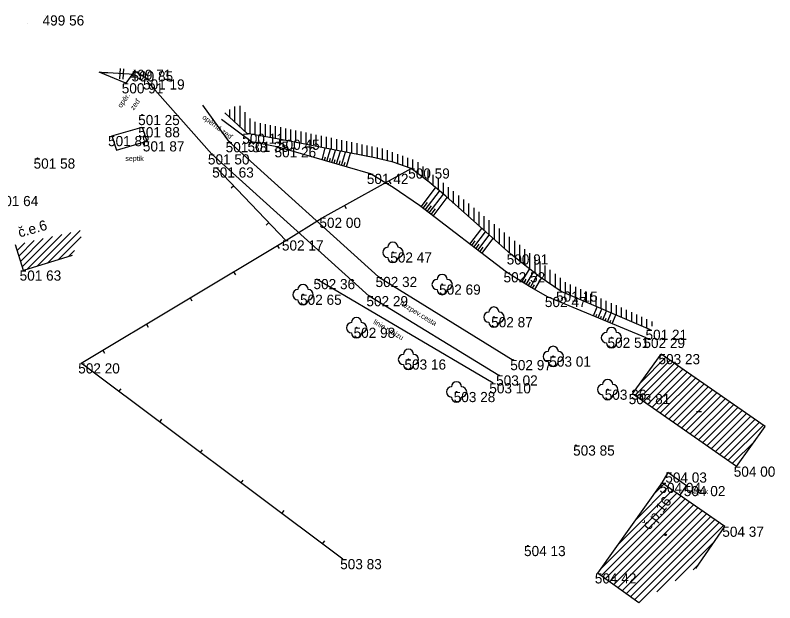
# Model space of a CAD drawing. Extents: x -554123 to -553118, y -1076825 to -1073672.
# Drawn here: x -553192.3 to -553117.7, y -1076813.9 to -1076756.1 of the extents above; entities that cross this region are included whole.
import ezdxf

# ---------------------------------------------------------------- set-up
doc = ezdxf.new("R2010")
doc.units = 0
for name, color, linetype in [('1', 7, 'Continuous'), ('12', 7, 'Continuous'), ('14', 7, 'Continuous'), ('17', 7, 'Continuous'), ('18', 7, 'Continuous'), ('26', 7, 'Continuous'), ('27', 7, 'Continuous'), ('28', 7, 'Continuous'), ('32', 7, 'Continuous'), ('34', 7, 'Continuous'), ('47', 7, 'Continuous'), ('52', 7, 'Continuous'), ('54', 7, 'Continuous'), ('6', 7, 'Continuous'), ('62', 7, 'Continuous')]:
    doc.layers.add(name, color=color, linetype=linetype)

# ---------------------------------------------------------------- blocks, each defined once
blk = doc.blocks.new('POINT_DISPLAY')
blk.add_line((0, 0), (0, 0))
blk = doc.blocks.new('T')
at = {"layer": '6'}
blk.add_circle((0, 0), 0.05, dxfattribs=at)
blk = doc.blocks.new('STL')
at = {"layer": '34'}
blk.add_circle((0, 0), 0.05, dxfattribs=at)
for centre, start, end in [((0, 0.5), 0, 180), ((-0.5, 0), 90, 270), ((0.5, 0), 270, 90), ((0, -0.5), 180, 0)]:
    blk.add_arc(centre, 0.5, start, end, dxfattribs=at)
blk = doc.blocks.new('BZ')
at = {"layer": '47'}
blk.add_circle((0, 0), 0.0875, dxfattribs=at)
blk = doc.blocks.new('BN')
at = {"layer": '47'}
blk.add_line((-0.25, 0), (0.25, 0), dxfattribs=at)
blk = doc.blocks.new('ROV')
at = {"layer": '62'}
for p, q in [((-0.348, -0.51), (-0.348, 0.51)), ((0, -0.51), (0, 0.51))]:
    blk.add_line(p, q, dxfattribs=at)

msp = doc.modelspace()

# ---------------------------------------------------------------- linework, layer by layer
at = {"layer": '12'}
for p, q in [((-553172.57, -1076771.05), (-553165.73, -1076778.23)), ((-553162.15, -1076776), (-553153.41, -1076771.15)), ((-553170.846, -1076772.86), (-553171.099, -1076773.102)), ((-553155.592, -1076772.361), (-553155.422, -1076772.667)), ((-553159.964, -1076774.787), (-553159.794, -1076775.093)), ((-553165.73, -1076778.23), (-553162.15, -1076776)), ((-553167.397, -1076776.48), (-553167.65, -1076776.722)), ((-553185.86, -1076790.32), (-553165.73, -1076778.23)), ((-553166.571, -1076778.735), (-553166.391, -1076779.035)), ((-553170.858, -1076781.31), (-553170.678, -1076781.61)), ((-553175.144, -1076783.884), (-553174.964, -1076784.184)), ((-553179.43, -1076786.458), (-553179.25, -1076786.759)), ((-553183.717, -1076789.033), (-553183.537, -1076789.333)), ((-553160.11, -1076809.58), (-553185.86, -1076790.32)), ((-553182.132, -1076793.109), (-553181.922, -1076792.828)), ((-553178.128, -1076796.104), (-553177.918, -1076795.823)), ((-553174.124, -1076799.098), (-553173.914, -1076798.818)), ((-553170.12, -1076802.093), (-553169.91, -1076801.813)), ((-553166.116, -1076805.088), (-553165.906, -1076804.808)), ((-553162.112, -1076808.083), (-553161.902, -1076807.802))]:
    msp.add_line(p, q, dxfattribs=at)
at = {"layer": '14'}
for p, q in [((-553191.5, -1076781.19), (-553192.288, -1076778.654)), ((-553186.725, -1076779.706), (-553191.5, -1076781.19)), ((-553131.64, -1076793.34), (-553128.82, -1076789.41)), ((-553118.61, -1076796.55), (-553128.82, -1076789.41)), ((-553121.43, -1076800.48), (-553131.64, -1076793.34)), ((-553121.43, -1076800.48), (-553118.61, -1076796.55)), ((-553128.75, -1076802.08), (-553135.1, -1076810.98)), ((-553122.56, -1076806.39), (-553128.75, -1076802.08)), ((-553125.417, -1076810.493), (-553122.56, -1076806.39)), ((-553131.03, -1076813.884), (-553135.1, -1076810.98))]:
    msp.add_line(p, q, dxfattribs=at)
at = {"layer": '17'}
for p, q in [((-553173, -1076769.76), (-553179.37, -1076762.58)), ((-553171.26, -1076768.56), (-553173.9, -1076764.93)), ((-553171.26, -1076768.56), (-553156.63, -1076781.82)), ((-553157.52, -1076783.71), (-553173, -1076769.76)), ((-553156.63, -1076781.82), (-553143.38, -1076790)), ((-553144.78, -1076791.51), (-553157.52, -1076783.71))]:
    msp.add_line(p, q, dxfattribs=at)
at = {"layer": '18'}
for p, q in [((-553180.62, -1076761.59), (-553181.46, -1076762.77)), ((-553179.26, -1076762.39), (-553180.62, -1076761.59)), ((-553169.11, -1076768.52), (-553172.04, -1076766.33)), ((-553182.82, -1076767.96), (-553179.85, -1076767.09)), ((-553179.85, -1076767.09), (-553179.4, -1076768.48)), ((-553182.82, -1076767.96), (-553182.37, -1076769.35)), ((-553182.37, -1076769.35), (-553179.4, -1076768.48)), ((-553169.307, -1076768.784), (-553169.11, -1076768.52)), ((-553128.16, -1076801.06), (-553128.75, -1076802.08)), ((-553126.34, -1076802.39), (-553128.16, -1076801.06)), ((-553126.982, -1076803.311), (-553126.34, -1076802.39))]:
    msp.add_line(p, q, dxfattribs=at)
at = {"layer": '26'}
for p, q in [((-553162.172, -1076770.296), (-553161.845, -1076769.165)), ((-553161.692, -1076770.435), (-553161.352, -1076769.26)), ((-553161.211, -1076770.574), (-553160.858, -1076769.355)), ((-553161.932, -1076770.365), (-553161.832, -1076770.02)), ((-553160.731, -1076770.713), (-553160.365, -1076769.45)), ((-553160.251, -1076770.852), (-553159.873, -1076769.545)), ((-553159.771, -1076770.991), (-553159.38, -1076769.64)), ((-553161.451, -1076770.504), (-553161.348, -1076770.145)), ((-553160.971, -1076770.643), (-553160.863, -1076770.271)), ((-553160.491, -1076770.782), (-553160.379, -1076770.397)), ((-553160.011, -1076770.921), (-553159.895, -1076770.523)), ((-553152.436, -1076774.918), (-553151, -1076773.048)), ((-553152.039, -1076775.223), (-553150.617, -1076773.373)), ((-553151.643, -1076775.527), (-553150.236, -1076773.696)), ((-553152.238, -1076775.07), (-553151.809, -1076774.512)), ((-553151.246, -1076775.832), (-553149.858, -1076774.025)), ((-553151.841, -1076775.375), (-553151.417, -1076774.823)), ((-553151.445, -1076775.679), (-553151.025, -1076775.133)), ((-553147.655, -1076778.591), (-553146.472, -1076777.051)), ((-553147.258, -1076778.895), (-553146.098, -1076777.385)), ((-553147.457, -1076778.743), (-553147.105, -1076778.286)), ((-553146.862, -1076779.2), (-553145.724, -1076777.719)), ((-553146.465, -1076779.505), (-553145.35, -1076778.054)), ((-553147.06, -1076779.048), (-553146.715, -1076778.599)), ((-553146.664, -1076779.352), (-553146.326, -1076778.912)), ((-553142.543, -1076782.295), (-553141.768, -1076781.047)), ((-553142.118, -1076782.559), (-553141.372, -1076781.357)), ((-553141.692, -1076782.82), (-553141.014, -1076781.637)), ((-553141.258, -1076783.069), (-553140.607, -1076781.933)), ((-553142.331, -1076782.427), (-553142.103, -1076782.06)), ((-553141.906, -1076782.691), (-553141.686, -1076782.337)), ((-553141.475, -1076782.944), (-553141.277, -1076782.598)), ((-553135.498, -1076785.658), (-553135.131, -1076784.774)), ((-553135.036, -1076785.85), (-553134.671, -1076784.971)), ((-553135.267, -1076785.754), (-553135.157, -1076785.49)), ((-553134.805, -1076785.946), (-553134.696, -1076785.683)), ((-553134.575, -1076786.042), (-553134.212, -1076785.167)), ((-553134.113, -1076786.233), (-553133.752, -1076785.364)), ((-553133.651, -1076786.425), (-553133.292, -1076785.56)), ((-553134.344, -1076786.138), (-553134.235, -1076785.876)), ((-553133.882, -1076786.329), (-553133.774, -1076786.069))]:
    msp.add_line(p, q, dxfattribs=at)
at = {"layer": '27'}
for p, q in [((-553181.46, -1076762.77), (-553184.07, -1076761.67)), ((-553166.44, -1076769.06), (-553169.11, -1076768.52)), ((-553157.39, -1076771.68), (-553166.44, -1076769.06)), ((-553130.29, -1076787.82), (-553140, -1076783.79))]:
    msp.add_line(p, q, dxfattribs=at)
for points in [[(-553144.05, -1076781.36), (-553152.579, -1076774.808), (-553155.161, -1076773.03), (-553157.39, -1076771.68)], [(-553140, -1076783.79), (-553141.772, -1076782.774), (-553144.05, -1076781.36)]]:
    msp.add_lwpolyline(points, dxfattribs=at)
at = {"layer": '28'}
for p, q in [((-553169.52, -1076767.73), (-553171.73, -1076765.67)), ((-553166.23, -1076768.32), (-553169.52, -1076767.73)), ((-553129.88, -1076787.02), (-553138.67, -1076783.26))]:
    msp.add_line(p, q, dxfattribs=at)
for points in [[(-553153.41, -1076771.15), (-553155.178, -1076770.537), (-553156.983, -1076770.102), (-553166.23, -1076768.32)], [(-553143.62, -1076779.6), (-553150.015, -1076773.884), (-553151.637, -1076772.507), (-553153.41, -1076771.15)], [(-553138.67, -1076783.26), (-553140.831, -1076781.78), (-553143.62, -1076779.6)]]:
    msp.add_lwpolyline(points, dxfattribs=at)
at = {"layer": '32'}
for p, q in [((-553171.23, -1076766.136), (-553171.23, -1076765.357)), ((-553170.73, -1076766.602), (-553170.73, -1076765.045)), ((-553170.23, -1076767.068), (-553170.23, -1076764.994)), ((-553169.73, -1076767.534), (-553169.73, -1076765.617)), ((-553169.23, -1076767.782), (-553169.23, -1076766.24)), ((-553168.73, -1076767.872), (-553168.73, -1076766.58)), ((-553168.23, -1076767.961), (-553168.23, -1076766.685)), ((-553167.73, -1076768.051), (-553167.73, -1076766.79)), ((-553167.23, -1076768.141), (-553167.23, -1076766.895)), ((-553166.73, -1076768.23), (-553166.73, -1076767)), ((-553166.23, -1076768.32), (-553166.23, -1076767.105)), ((-553165.73, -1076768.416), (-553165.73, -1076767.21)), ((-553165.23, -1076768.513), (-553165.23, -1076767.315)), ((-553164.73, -1076768.609), (-553164.73, -1076767.42)), ((-553164.23, -1076768.705), (-553164.23, -1076767.525)), ((-553163.73, -1076768.802), (-553163.73, -1076767.63)), ((-553163.23, -1076768.898), (-553163.23, -1076767.735)), ((-553162.73, -1076768.994), (-553162.73, -1076767.84)), ((-553162.23, -1076769.091), (-553162.23, -1076767.945)), ((-553161.73, -1076769.187), (-553161.73, -1076768.05)), ((-553161.23, -1076769.284), (-553161.23, -1076768.155)), ((-553160.73, -1076769.38), (-553160.73, -1076768.26)), ((-553160.23, -1076769.476), (-553160.23, -1076768.366)), ((-553159.73, -1076769.573), (-553159.73, -1076768.471)), ((-553159.23, -1076769.669), (-553159.23, -1076768.576)), ((-553158.73, -1076769.765), (-553158.73, -1076768.681)), ((-553158.23, -1076769.862), (-553158.23, -1076768.786)), ((-553157.73, -1076769.958), (-553157.73, -1076768.891)), ((-553157.23, -1076770.054), (-553157.23, -1076768.996)), ((-553156.73, -1076770.163), (-553156.73, -1076769.101)), ((-553156.23, -1076770.283), (-553156.23, -1076769.206)), ((-553155.73, -1076770.404), (-553155.73, -1076769.37)), ((-553155.23, -1076770.524), (-553155.23, -1076769.553)), ((-553154.73, -1076770.692), (-553154.73, -1076769.737)), ((-553154.23, -1076770.866), (-553154.23, -1076769.92)), ((-553153.73, -1076771.039), (-553153.73, -1076770.104)), ((-553153.23, -1076771.288), (-553153.23, -1076770.287)), ((-553152.73, -1076771.67), (-553152.73, -1076770.549)), ((-553152.23, -1076772.053), (-553152.23, -1076770.955)), ((-553151.73, -1076772.436), (-553151.73, -1076771.362)), ((-553151.23, -1076772.853), (-553151.23, -1076771.768)), ((-553150.73, -1076773.277), (-553150.73, -1076772.175)), ((-553150.23, -1076773.701), (-553150.23, -1076772.581)), ((-553149.73, -1076774.139), (-553149.73, -1076772.987)), ((-553149.23, -1076774.586), (-553149.23, -1076773.394)), ((-553148.73, -1076775.033), (-553148.73, -1076773.8)), ((-553148.23, -1076775.479), (-553148.23, -1076774.206)), ((-553147.73, -1076775.926), (-553147.73, -1076774.613)), ((-553147.23, -1076776.373), (-553147.23, -1076775.019)), ((-553146.73, -1076776.82), (-553146.73, -1076775.426)), ((-553146.23, -1076777.267), (-553146.23, -1076775.832)), ((-553145.73, -1076777.714), (-553145.73, -1076776.238)), ((-553145.23, -1076778.161), (-553145.23, -1076776.645)), ((-553190.167, -1076780.776), (-553186.852, -1076777.461)), ((-553189.141, -1076780.457), (-553185.946, -1076777.262)), ((-553144.73, -1076778.608), (-553144.73, -1076777.051)), ((-553144.23, -1076779.055), (-553144.23, -1076777.457)), ((-553191.953, -1076779.733), (-553190.476, -1076778.256)), ((-553191.785, -1076780.272), (-553189.57, -1076778.057)), ((-553191.617, -1076780.812), (-553188.664, -1076777.858)), ((-553191.193, -1076781.095), (-553187.758, -1076777.66)), ((-553188.115, -1076780.138), (-553185.851, -1076777.874)), ((-553143.73, -1076779.502), (-553143.73, -1076777.864)), ((-553143.23, -1076779.905), (-553143.23, -1076778.27)), ((-553192.12, -1076779.193), (-553191.382, -1076778.455)), ((-553142.73, -1076780.296), (-553142.73, -1076778.677)), ((-553187.089, -1076779.819), (-553186.496, -1076779.226)), ((-553142.23, -1076780.686), (-553142.23, -1076779.083)), ((-553141.73, -1076781.077), (-553141.73, -1076779.489)), ((-553141.23, -1076781.468), (-553141.23, -1076779.896)), ((-553140.73, -1076781.849), (-553140.73, -1076780.302)), ((-553140.23, -1076782.192), (-553140.23, -1076780.708)), ((-553139.73, -1076782.534), (-553139.73, -1076781.115)), ((-553139.23, -1076782.876), (-553139.23, -1076781.521)), ((-553138.73, -1076783.219), (-553138.73, -1076781.928)), ((-553138.23, -1076783.448), (-553138.23, -1076782.334)), ((-553137.73, -1076783.662), (-553137.73, -1076782.583)), ((-553137.23, -1076783.876), (-553137.23, -1076782.809)), ((-553136.73, -1076784.09), (-553136.73, -1076783.035)), ((-553136.23, -1076784.304), (-553136.23, -1076783.261)), ((-553135.73, -1076784.518), (-553135.73, -1076783.487)), ((-553135.23, -1076784.731), (-553135.23, -1076783.713)), ((-553134.73, -1076784.945), (-553134.73, -1076783.94)), ((-553134.23, -1076785.159), (-553134.23, -1076784.166)), ((-553133.73, -1076785.373), (-553133.73, -1076784.392)), ((-553133.23, -1076785.587), (-553133.23, -1076784.618)), ((-553132.73, -1076785.801), (-553132.73, -1076784.844)), ((-553132.23, -1076786.015), (-553132.23, -1076785.07)), ((-553131.73, -1076786.229), (-553131.73, -1076785.296)), ((-553131.23, -1076786.443), (-553131.23, -1076785.522)), ((-553130.73, -1076786.656), (-553130.73, -1076785.748)), ((-553130.23, -1076786.87), (-553130.23, -1076785.974)), ((-553129.73, -1076786.662), (-553129.73, -1076786.2)), ((-553129.011, -1076789.676), (-553128.776, -1076789.441)), ((-553131.417, -1076793.496), (-553127.944, -1076790.023)), ((-553130.808, -1076792.18), (-553128.36, -1076789.732)), ((-553131.001, -1076793.787), (-553127.527, -1076790.314)), ((-553130.584, -1076794.078), (-553127.111, -1076790.605)), ((-553130.168, -1076794.369), (-553126.695, -1076790.896)), ((-553129.752, -1076794.66), (-553126.279, -1076791.187)), ((-553129.336, -1076794.951), (-553125.863, -1076791.478)), ((-553128.92, -1076795.242), (-553125.447, -1076791.769)), ((-553128.504, -1076795.533), (-553125.031, -1076792.06)), ((-553128.088, -1076795.824), (-553124.615, -1076792.351)), ((-553127.672, -1076796.115), (-553124.198, -1076792.642)), ((-553127.256, -1076796.406), (-553123.782, -1076792.933)), ((-553126.839, -1076796.697), (-553123.366, -1076793.224)), ((-553126.423, -1076796.988), (-553122.95, -1076793.515)), ((-553126.007, -1076797.279), (-553122.534, -1076793.806)), ((-553125.591, -1076797.57), (-553122.118, -1076794.097)), ((-553125.175, -1076797.861), (-553121.702, -1076794.388)), ((-553124.759, -1076798.152), (-553121.286, -1076794.679)), ((-553124.343, -1076798.443), (-553120.87, -1076794.97)), ((-553123.927, -1076798.734), (-553120.453, -1076795.261)), ((-553123.511, -1076799.025), (-553120.037, -1076795.552)), ((-553123.094, -1076799.316), (-553119.621, -1076795.843)), ((-553122.678, -1076799.607), (-553119.205, -1076796.134)), ((-553122.262, -1076799.898), (-553118.789, -1076796.425)), ((-553121.846, -1076800.189), (-553119.634, -1076797.976)), ((-553129.576, -1076803.237), (-553128.555, -1076802.216)), ((-553133.097, -1076808.173), (-553127.721, -1076802.797)), ((-553131.337, -1076805.705), (-553128.138, -1076802.506)), ((-553134.858, -1076810.641), (-553127.304, -1076803.087)), ((-553134.744, -1076811.234), (-553126.887, -1076803.377)), ((-553134.331, -1076811.528), (-553126.47, -1076803.667)), ((-553133.919, -1076811.823), (-553126.053, -1076803.958)), ((-553133.506, -1076812.117), (-553125.637, -1076804.248)), ((-553133.093, -1076812.412), (-553125.22, -1076804.538)), ((-553132.681, -1076812.706), (-553124.803, -1076804.828)), ((-553132.268, -1076813.001), (-553124.386, -1076805.119)), ((-553131.855, -1076813.295), (-553123.969, -1076805.409)), ((-553131.443, -1076813.59), (-553123.552, -1076805.699)), ((-553131.03, -1076813.884), (-553123.135, -1076805.989)), ((-553129.244, -1076812.805), (-553122.719, -1076806.28)), ((-553127.458, -1076811.726), (-553123.565, -1076807.833)), ((-553125.671, -1076810.647), (-553125.186, -1076810.161))]:
    msp.add_line(p, q, dxfattribs=at)
at = {"layer": '34'}
msp.add_line((-553145.34, -1076792.28), (-553162.72, -1076782.03), dxfattribs=at)
at = {"layer": '62'}
for p, q in [((-553183.617, -1076761.735), (-553184.07, -1076761.67)), ((-553183.227, -1076761.762), (-553183.617, -1076761.735)), ((-553180.6, -1076761.91), (-553183.227, -1076761.762))]:
    msp.add_line(p, q, dxfattribs=at)

# ---------------------------------------------------------------- block references
at = {"layer": '1'}
for p in [(-553189.34, -1076756.09), (-553180.68, -1076761.44), (-553180.62, -1076761.59), (-553179.26, -1076762.39), (-553181.46, -1076762.77), (-553179.86, -1076765.89), (-553179.85, -1076767.09), (-553169.52, -1076767.73), (-553182.82, -1076767.96), (-553179.4, -1076768.48), (-553171.26, -1076768.56), (-553169.11, -1076768.52), (-553166.23, -1076768.32), (-553166.44, -1076769.06), (-553173, -1076769.76), (-553190.14, -1076770.17), (-553172.57, -1076771.05), (-553153.41, -1076771.15), (-553157.39, -1076771.68), (-553162.15, -1076776), (-553165.73, -1076778.23), (-553155.2, -1076779.41), (-553143.62, -1076779.6), (-553191.5, -1076781.19), (-553162.72, -1076782.03), (-553156.63, -1076781.82), (-553144.05, -1076781.36), (-553150.36, -1076782.57), (-553138.67, -1076783.26), (-553164.04, -1076783.57), (-553157.52, -1076783.71), (-553140, -1076783.79), (-553145.27, -1076785.78), (-553158.78, -1076786.82), (-553129.88, -1076787.02), (-553133.72, -1076787.8), (-553130.29, -1076787.82), (-553128.82, -1076789.41), (-553153.67, -1076789.94), (-553143.38, -1076790), (-553139.44, -1076789.65), (-553185.86, -1076790.32), (-553144.78, -1076791.51), (-553145.34, -1076792.28), (-553148.95, -1076793.14), (-553134.09, -1076792.91), (-553131.64, -1076793.34), (-553137.21, -1076798.4), (-553121.43, -1076800.48), (-553128.16, -1076801.06), (-553128.75, -1076802.08), (-553126.34, -1076802.39), (-553122.56, -1076806.39), (-553141.94, -1076808.29), (-553160.11, -1076809.58), (-553135.1, -1076810.98)]:
    msp.add_blockref('POINT_DISPLAY', p, dxfattribs=at)
at = {"layer": '32'}
for p in [(-553192.288, -1076778.654), (-553131.03, -1076813.884)]:
    msp.add_blockref('POINT_DISPLAY', p, dxfattribs=at)
at = {"layer": '34'}
for p in [(-553155.2, -1076779.41), (-553150.36, -1076782.57), (-553164.04, -1076783.57), (-553145.27, -1076785.78), (-553158.78, -1076786.82), (-553133.72, -1076787.8), (-553139.44, -1076789.65), (-553153.67, -1076789.94), (-553148.95, -1076793.14), (-553134.09, -1076792.91)]:
    msp.add_blockref('STL', p, dxfattribs=at)
at = {"layer": '47'}
for name, p in [('BN', (-553125.11, -1076795.051)), ('BZ', (-553128.409, -1076807.189))]:
    msp.add_blockref(name, p, dxfattribs=at)
at = {"layer": '6'}
for p in [(-553179.86, -1076765.89), (-553171.26, -1076768.56), (-553173, -1076769.76), (-553190.14, -1076770.17), (-553156.63, -1076781.82), (-553157.52, -1076783.71), (-553143.38, -1076790), (-553144.78, -1076791.51), (-553137.21, -1076798.4), (-553141.94, -1076808.29)]:
    msp.add_blockref('T', p, dxfattribs=at)
at = {"layer": '62'}
msp.add_blockref('POINT_DISPLAY', (-553191.15, -1076756.92), dxfattribs=at)
at = {"layer": '62', "xscale": 0.9999998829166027, "yscale": 0.9999998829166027, "rotation": 176.77556368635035}
msp.add_blockref('ROV', (-553182.056, -1076761.843), dxfattribs=at)

# ---------------------------------------------------------------- texts
at = {"layer": '52'}
for s, rotation, p in [('opěr.', 54.55429, (-553181.908, -1076765.233)), ('zeď', 54.55429, (-553180.679, -1076765.454)), ('opěrná zeď', 323.22408, (-553173.99, -1076766.218)), ('nezpev.cesta', 328.52316, (-553154.559, -1076784.544)), ('linie rybízu', 329.46967, (-553157.177, -1076786.388))]:
    msp.add_text(s, height=0.5, rotation=rotation, dxfattribs=at).set_placement(p)
for p in [(-553181.5, -1076770.415), (-553126.03, -1076803.182)]:
    msp.add_text('septik', height=0.5, dxfattribs=at).set_placement(p)
at = {"layer": '54'}
for s, rotation, p in [('č.e.6', 16.02692, (-553191.891, -1076777.956)), ('č.p.16', 52.13267, (-553129.992, -1076806.798))]:
    msp.add_text(s, height=1, rotation=rotation, dxfattribs=at).set_placement(p)
at = {"layer": '6'}
for s, p in [('499 56 ', (-553189.638, -1076757.09)), ('499 71 ', (-553181.071, -1076762.44)), ('500 85 ', (-553180.898, -1076762.59)), ('501 19 ', (-553179.766, -1076763.39)), ('500 91 ', (-553181.857, -1076763.77)), ('501 25 ', (-553180.245, -1076766.89)), ('501 88 ', (-553180.235, -1076768.09)), ('500 11 ', (-553170.014, -1076768.73)), ('501 88 ', (-553183.205, -1076768.96)), ('501 87 ', (-553179.783, -1076769.48)), ('501 38 ', (-553171.645, -1076769.56)), ('501 35 ', (-553169.495, -1076769.52)), ('500 45 ', (-553166.496, -1076769.32)), ('501 26 ', (-553166.837, -1076770.06)), ('501 50 ', (-553173.387, -1076770.76)), ('501 58 ', (-553190.525, -1076771.17)), ('501 63 ', (-553172.967, -1076772.05)), ('500 59 ', (-553153.7, -1076772.15)), ('501 42 ', (-553157.763, -1076772.68)), ('501 64 ', (-553194.155, -1076774.86)), ('502 00 ', (-553162.43, -1076777)), ('502 17 ', (-553166.113, -1076779.23)), ('502 47 ', (-553155.462, -1076780.41)), ('500 91 ', (-553144.017, -1076780.6)), ('501 63 ', (-553191.897, -1076782.19)), ('502 36 ', (-553163.008, -1076783.03)), ('502 32 ', (-553156.906, -1076782.82)), ('502 52 ', (-553144.326, -1076782.36)), ('502 69 ', (-553150.66, -1076783.57)), ('501 15 ', (-553139.164, -1076784.26)), ('502 65 ', (-553164.328, -1076784.57)), ('502 29 ', (-553157.808, -1076784.71)), ('502 47 ', (-553140.262, -1076784.79)), ('502 87 ', (-553145.544, -1076786.78)), ('502 98 ', (-553159.068, -1076787.82)), ('501 21 ', (-553130.372, -1076788.02)), ('502 51 ', (-553134.103, -1076788.8)), ('502 29 ', (-553130.578, -1076788.82)), ('503 23 ', (-553129.096, -1076790.41)), ('503 16 ', (-553154.067, -1076790.94)), ('502 97 ', (-553143.666, -1076791)), ('503 01 ', (-553139.825, -1076790.65)), ('502 20 ', (-553186.138, -1076791.32)), ('503 02 ', (-553145.058, -1076792.51)), ('503 10 ', (-553145.727, -1076793.28)), ('503 28 ', (-553149.226, -1076794.14)), ('503 36 ', (-553134.378, -1076793.91)), ('503 81 ', (-553132.023, -1076794.34)), ('503 85 ', (-553137.486, -1076799.4)), ('504 00 ', (-553121.698, -1076801.48)), ('504 03 ', (-553128.426, -1076802.06)), ('504 04 ', (-553129.004, -1076803.08)), ('504 02 ', (-553126.606, -1076803.39)), ('504 37 ', (-553122.822, -1076807.39)), ('504 13 ', (-553142.313, -1076809.29)), ('503 83 ', (-553160.386, -1076810.58)), ('504 42 ', (-553135.352, -1076811.98))]:
    msp.add_text(s, height=1, dxfattribs=at).set_placement(p)

doc.saveas('drawing.dxf')
